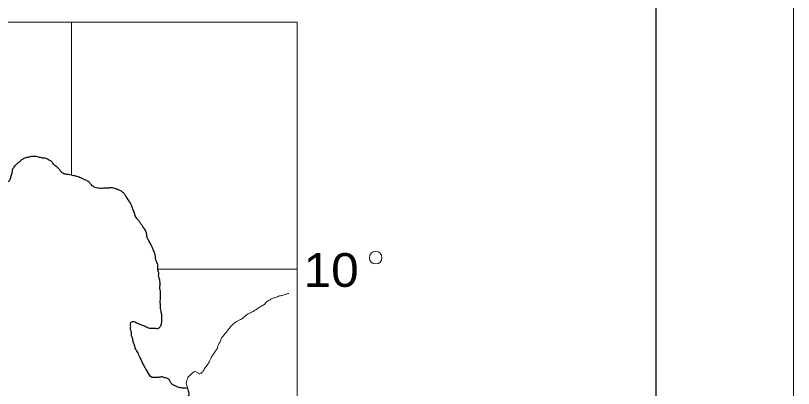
# Model space of a CAD drawing. Extents: x 854879 to 917879, y 8541948 to 8631048.
# Drawn here: x 909782 to 917879, y 8557163 to 8561047 of the extents above; entities that cross this region are included whole.
import ezdxf
from ezdxf.enums import TextEntityAlignment as Align

# ---------------------------------------------------------------- set-up
doc = ezdxf.new("R2010")
doc.units = 0
doc.header["$LTSCALE"] = 160
for name, color, linetype, lineweight in [('1', 7, 'Continuous', 13), ('36', 7, 'Continuous', 13), ('44', 7, 'Continuous', 13), ('63', 7, 'Continuous', 13)]:
    doc.layers.add(name, color=color, linetype=linetype, lineweight=lineweight)

msp = doc.modelspace()

# ---------------------------------------------------------------- linework, layer by layer
at = {"layer": '1'}
msp.add_lwpolyline([(916445.6, 8586427.1), (916445.6, 8544954.2), (858846.4, 8544954.2), (858846.4, 8599885.6)], dxfattribs=at)
at = {"layer": '36'}
msp.add_lwpolyline([(854878.6, 8541948.4), (917878.6, 8541948.4), (917878.6, 8631048.4), (854878.6, 8631048.4)], close=True, dxfattribs=at)
at = {"layer": '36', "lineweight": 25}
msp.add_lwpolyline([(858846.4, 8628560.7), (916445.6, 8628560.7), (916445.6, 8544954.2), (858846.4, 8544954.2)], close=True, dxfattribs=at)
at = {"layer": '44'}
msp.add_lwpolyline([(858846.4, 8628560.7), (916445.6, 8628560.7), (916445.6, 8544954.2), (858846.4, 8544954.2)], close=True, dxfattribs=at)
at = {"layer": '63'}
for p, q in [((910363.3, 8560979), (910363.3, 8559384.7)), ((911262.5, 8558404.9), (912712.9, 8558404.9)), ((911575.8, 8557163.5), (911557.9, 8557166.3))]:
    msp.add_line(p, q, dxfattribs=at)
msp.add_lwpolyline([(912712.9, 8560979), (903413.8, 8560979), (903413.8, 8550908.8), (912712.9, 8550908.8)], close=True, dxfattribs=at)
msp.add_circle((913529.5, 8558524.8), 65.1, dxfattribs=at)
at = {"layer": '63', "lineweight": 25}
for points in [[(910471.7, 8559350), (910423, 8559371.5), (910387, 8559379.4), (910334.6, 8559391.1), (910295.3, 8559395.8), (910256.3, 8559420.2), (910237.2, 8559447.2), (910205, 8559474.8), (910169.6, 8559509.1), (910150.4, 8559532.9), (910124.4, 8559543.7), (910101.6, 8559557.6), (910072.1, 8559562), (910029.6, 8559570.1), (909954.2, 8559579.3), (909914.6, 8559570.8), (909878.2, 8559562.2), (909844.9, 8559543.4), (909814.8, 8559518.1), (909791.3, 8559499.1), (909771.2, 8559476.8), (909750.8, 8559444.4), (909743.3, 8559408.4), (909732.8, 8559375.8), (909722, 8559336.5), (909701.9, 8559314), (909668.8, 8559305.3), (909635.8, 8559299.8), (909586.6, 8559301.5), (909553.7, 8559302.7), (909520.9, 8559303.9), (909510.4, 8559274.5), (909509.3, 8559231.6), (909492.2, 8559195.8), (909468.9, 8559183.5), (909419.6, 8559185.2), (909386.8, 8559186.3), (909360.2, 8559174), (909359.7, 8559147.6), (909355, 8559085.1), (909341.1, 8559052.6), (909314.3, 8559030.3), (909281.1, 8559011.8), (909241.4, 8558999.9), (909214.9, 8558994.2), (909175.4, 8558985.6), (909138.7, 8558967.2), (909108.9, 8558954.9), (909075.9, 8558949.5), (909046.3, 8558943.9), (909010.1, 8558945.2), (908987.5, 8558962.5), (908988.4, 8559008.6), (908989.1, 8559035), (908979.7, 8559061.8), (908960.7, 8559095.5), (908931.8, 8559119.5), (908909.1, 8559136.9), (908873.5, 8559161.2), (908847.4, 8559168.8), (908841.7, 8559205.2), (908848.9, 8559238.1), (908849.6, 8559271), (908843.9, 8559307.5), (908811.6, 8559338.3), (908749.5, 8559353.8), (908713.3, 8559354.9), (908687.2, 8559362.5), (908648.1, 8559373.8), (908586.1, 8559392.4), (908556.7, 8559403.3), (908520.8, 8559414.5), (908487.9, 8559412.3), (908454.7, 8559396.9), (908421.5, 8559385), (908398.2, 8559369.2), (908354.7, 8559334.4), (908341, 8559311.8), (908324.1, 8559289.3), (908306.8, 8559250.3), (908289.3, 8559198), (908282, 8559168.5), (908251.8, 8559143.2), (908222, 8559124.5), (908191.9, 8559105.6), (908162, 8559093.5), (908115.9, 8559085.2), (908076.3, 8559083.2), (908050.1, 8559084.2), (908024, 8559091.7), (907978.1, 8559096.6)], [(910471.7, 8559350), (910423, 8559371.5), (910387, 8559379.4), (910334.6, 8559391.1), (910295.3, 8559395.8), (910256.3, 8559420.2), (910237.2, 8559447.2), (910205, 8559474.8), (910169.6, 8559509.1), (910150.4, 8559532.9), (910124.4, 8559543.7), (910101.6, 8559557.6), (910072.1, 8559562), (910029.6, 8559570.1), (909954.2, 8559579.3), (909914.6, 8559570.8), (909878.2, 8559562.2), (909844.9, 8559543.4), (909814.8, 8559518.1), (909791.3, 8559499.1), (909771.2, 8559476.8), (909750.8, 8559444.4), (909743.3, 8559408.4), (909732.8, 8559375.8), (909722, 8559336.5), (909701.9, 8559314), (909668.8, 8559305.3), (909635.8, 8559299.8), (909586.6, 8559301.5), (909553.7, 8559302.7), (909520.9, 8559303.9), (909510.4, 8559274.5), (909509.3, 8559231.6), (909492.2, 8559195.8), (909468.9, 8559183.5), (909419.6, 8559185.2), (909386.8, 8559186.3), (909360.2, 8559174), (909359.7, 8559147.6), (909355, 8559085.1), (909341.1, 8559052.6), (909314.3, 8559030.3), (909281.1, 8559011.8), (909241.4, 8558999.9), (909214.9, 8558994.2), (909175.4, 8558985.6), (909138.7, 8558967.2), (909108.9, 8558954.9), (909075.9, 8558949.5), (909046.3, 8558943.9), (909010.1, 8558945.2), (908987.5, 8558962.5), (908988.4, 8559008.6), (908989.1, 8559035), (908979.7, 8559061.8), (908960.7, 8559095.5), (908931.8, 8559119.5), (908909.1, 8559136.9), (908873.5, 8559161.2), (908847.4, 8559168.8), (908841.7, 8559205.2), (908848.9, 8559238.1), (908849.6, 8559271), (908843.9, 8559307.5), (908811.6, 8559338.3), (908749.5, 8559353.8), (908713.3, 8559354.9), (908687.2, 8559362.5), (908648.1, 8559373.8), (908586.1, 8559392.4), (908556.7, 8559403.3), (908520.8, 8559414.5), (908487.9, 8559412.3), (908454.7, 8559396.9), (908421.5, 8559385), (908398.2, 8559369.2), (908354.7, 8559334.4), (908341, 8559311.8), (908324.1, 8559289.3), (908306.8, 8559250.3), (908289.3, 8559198), (908282, 8559168.5), (908251.8, 8559143.2), (908222, 8559124.5), (908191.9, 8559105.6), (908162, 8559093.5), (908115.9, 8559085.2), (908076.3, 8559083.2), (908050.1, 8559084.2), (908024, 8559091.7), (907978.1, 8559096.6)], [(911557.9, 8557166.3), (911531.5, 8557167.2), (911489, 8557172), (911456.3, 8557183), (911427, 8557197.2), (911404.3, 8557214.5), (911388.6, 8557241.5), (911369.4, 8557265.2), (911343.2, 8557272.7), (911310.6, 8557283.8), (911271.1, 8557278.6), (911238.1, 8557276.4), (911195.6, 8557281.2), (911166.7, 8557318.5), (911141.4, 8557359.1), (911122.4, 8557392.7), (911109.8, 8557416.3), (911090.9, 8557459.8), (911078.3, 8557483.3), (911053.2, 8557537), (911028, 8557584.2), (911018.8, 8557617.5), (911006.3, 8557647.7), (911000.6, 8557687.4), (910988.1, 8557717.6), (910988.7, 8557744), (910979.5, 8557774), (910980.3, 8557810.3), (910981.1, 8557846.6), (911004.5, 8557862.3), (911040.3, 8557847.9), (911072.8, 8557833.6), (911099, 8557822.8), (911125.1, 8557815.2), (911154.2, 8557797.7), (911200.1, 8557792.7), (911229.8, 8557791.7), (911269.2, 8557790.4), (911292.7, 8557816), (911303.5, 8557855.3), (911304.1, 8557884.9), (911304.8, 8557917.9), (911299.1, 8557954.5), (911293.1, 8557981.1), (911290.3, 8558010.9), (911288.5, 8558073.7), (911289.3, 8558109.9), (911290, 8558143), (911290.7, 8558176), (911284.8, 8558202.5), (911285.5, 8558238.8), (911286.2, 8558268.5), (911277.3, 8558311.7), (911271.4, 8558341.7), (911271.9, 8558368.1), (911262.8, 8558398.2), (911263.6, 8558434.4), (911257.6, 8558464.3), (911242.1, 8558504.5), (911236.5, 8558554.2), (911217.9, 8558601.1), (911205.5, 8558634.5), (911189.7, 8558664.8), (911167.6, 8558705.2), (911151.8, 8558735.4), (911146.2, 8558775.3), (911133.7, 8558808.7), (911111.5, 8558842.5), (911092.3, 8558869.5), (911073.2, 8558899.9), (911050.9, 8558927.1), (911028.5, 8558960.9), (911019.4, 8558994.2), (910997.6, 8559044.5), (910985.1, 8559077.9), (910969.2, 8559105), (910931.2, 8559165.7), (910912, 8559192.7), (910882.9, 8559216.9), (910853.7, 8559231.1), (910824.4, 8559242), (910778.7, 8559253.6), (910742.4, 8559248.2), (910712.8, 8559249.3), (910683.1, 8559246.9), (910650.3, 8559248.1), (910598.1, 8559263), (910565.7, 8559290.6), (910540.1, 8559317.9), (910504.4, 8559335.7), (910471.7, 8559350)], [(911557.9, 8557166.3), (911531.5, 8557167.2), (911489, 8557172), (911456.3, 8557183), (911427, 8557197.2), (911404.3, 8557214.5), (911388.6, 8557241.5), (911369.4, 8557265.2), (911343.2, 8557272.7), (911310.6, 8557283.8), (911271.1, 8557278.6), (911238.1, 8557276.4), (911195.6, 8557281.2), (911166.7, 8557318.5), (911141.4, 8557359.1), (911122.4, 8557392.7), (911109.8, 8557416.3), (911090.9, 8557459.8), (911078.3, 8557483.3), (911053.2, 8557537), (911028, 8557584.2), (911018.8, 8557617.5), (911006.3, 8557647.7), (911000.6, 8557687.4), (910988.1, 8557717.6), (910988.7, 8557744), (910979.5, 8557774), (910980.3, 8557810.3), (910981.1, 8557846.6), (911004.5, 8557862.3), (911040.3, 8557847.9), (911072.8, 8557833.6), (911099, 8557822.8), (911125.1, 8557815.2), (911154.2, 8557797.7), (911200.1, 8557792.7), (911229.8, 8557791.7), (911269.2, 8557790.4), (911292.7, 8557816), (911303.5, 8557855.3), (911304.1, 8557884.9), (911304.8, 8557917.9), (911299.1, 8557954.5), (911293.1, 8557981.1), (911290.3, 8558010.9), (911288.5, 8558073.7), (911289.3, 8558109.9), (911290, 8558143), (911290.7, 8558176), (911284.8, 8558202.5), (911285.5, 8558238.8), (911286.2, 8558268.5), (911277.3, 8558311.7), (911271.4, 8558341.7), (911271.9, 8558368.1), (911262.8, 8558398.2), (911263.6, 8558434.4), (911257.6, 8558464.3), (911242.1, 8558504.5), (911236.5, 8558554.2), (911217.9, 8558601.1), (911205.5, 8558634.5), (911189.7, 8558664.8), (911167.6, 8558705.2), (911151.8, 8558735.4), (911146.2, 8558775.3), (911133.7, 8558808.7), (911111.5, 8558842.5), (911092.3, 8558869.5), (911073.2, 8558899.9), (911050.9, 8558927.1), (911028.5, 8558960.9), (911019.4, 8558994.2), (910997.6, 8559044.5), (910985.1, 8559077.9), (910969.2, 8559105), (910931.2, 8559165.7), (910912, 8559192.7), (910882.9, 8559216.9), (910853.7, 8559231.1), (910824.4, 8559242), (910778.7, 8559253.6), (910742.4, 8559248.2), (910712.8, 8559249.3), (910683.1, 8559246.9), (910650.3, 8559248.1), (910598.1, 8559263), (910565.7, 8559290.6), (910540.1, 8559317.9), (910504.4, 8559335.7), (910471.7, 8559350)], [(910499.8, 8556281.9), (910529.5, 8556284.2), (910565.5, 8556276.3), (910597.7, 8556252.1), (910626.8, 8556227.9), (910652.7, 8556210.5), (910678.6, 8556193.1), (910711.3, 8556185.4), (910746.8, 8556157.7), (910746.3, 8556131.3), (910755.4, 8556094.7), (910761, 8556051.7), (910787.1, 8556047.4), (910816.9, 8556052.9), (910853.7, 8556081.4), (910887.3, 8556119.9), (910907.5, 8556139), (910937.8, 8556167.6), (910964.7, 8556199.7), (910991.6, 8556225.2), (911031.9, 8556266.7), (911062.2, 8556295.4), (911082.3, 8556317.8), (911109.2, 8556343.2), (911139.7, 8556381.8), (911156.6, 8556407.6), (911180.4, 8556439.8), (911204, 8556468.7), (911227.6, 8556494.3), (911244.7, 8556526.8), (911265, 8556552.4), (911282, 8556578.3), (911299.2, 8556614), (911319.7, 8556652.9), (911336.9, 8556682), (911364.3, 8556733.9), (911391.6, 8556779.1), (911412.2, 8556818.1), (911429.4, 8556860.4), (911446.6, 8556892.8), (911463.9, 8556928.5), (911480.9, 8556957.6), (911514.8, 8557006), (911541.9, 8557041.3), (911558.9, 8557063.8), (911589.2, 8557099.2), (911583.5, 8557135.7), (911575.8, 8557163.5)]]:
    msp.add_spline(points, degree=3, dxfattribs=at)
at = {"layer": '63'}
msp.add_spline([(912624.9, 8558153.6), (912594.9, 8558143.9), (912568.4, 8558134.8), (912528.7, 8558126.3), (912485.7, 8558111.2), (912452.5, 8558099.3), (912426, 8558083.7), (912402.6, 8558071.2), (912372.3, 8558039.3), (912335.8, 8558017.5), (912295.8, 8557992.4), (912239.1, 8557958.1), (912192.5, 8557933.3), (912159.1, 8557904.8), (912115.7, 8557876.6), (912089.2, 8557864.2), (912055.8, 8557842.3), (912018.9, 8557803.9), (911991.8, 8557771.9), (911968.2, 8557739.7), (911941.1, 8557707.6), (911920.7, 8557678.6), (911906.8, 8557642.7), (911889.6, 8557610.3), (911879.1, 8557577.7), (911858.7, 8557548.7), (911845.1, 8557526.1), (911824.6, 8557493.7), (911811, 8557467.9), (911797.2, 8557438.6), (911773.4, 8557403.1), (911746.2, 8557364.4), (911722.5, 8557328.9), (911692.6, 8557316.8), (911669.9, 8557334.1), (911637.2, 8557335.1), (911610.4, 8557313), (911576.7, 8557277.8), (911566.2, 8557248.6), (911558.9, 8557215.8), (911573.7, 8557170.7)], degree=3, dxfattribs=at)

# ---------------------------------------------------------------- texts
at = {"layer": '63', "width": 1.1}
msp.add_text('10', height=351, dxfattribs=at).set_placement((913354, 8558221.6), align=Align.RIGHT)

doc.saveas('drawing.dxf')
